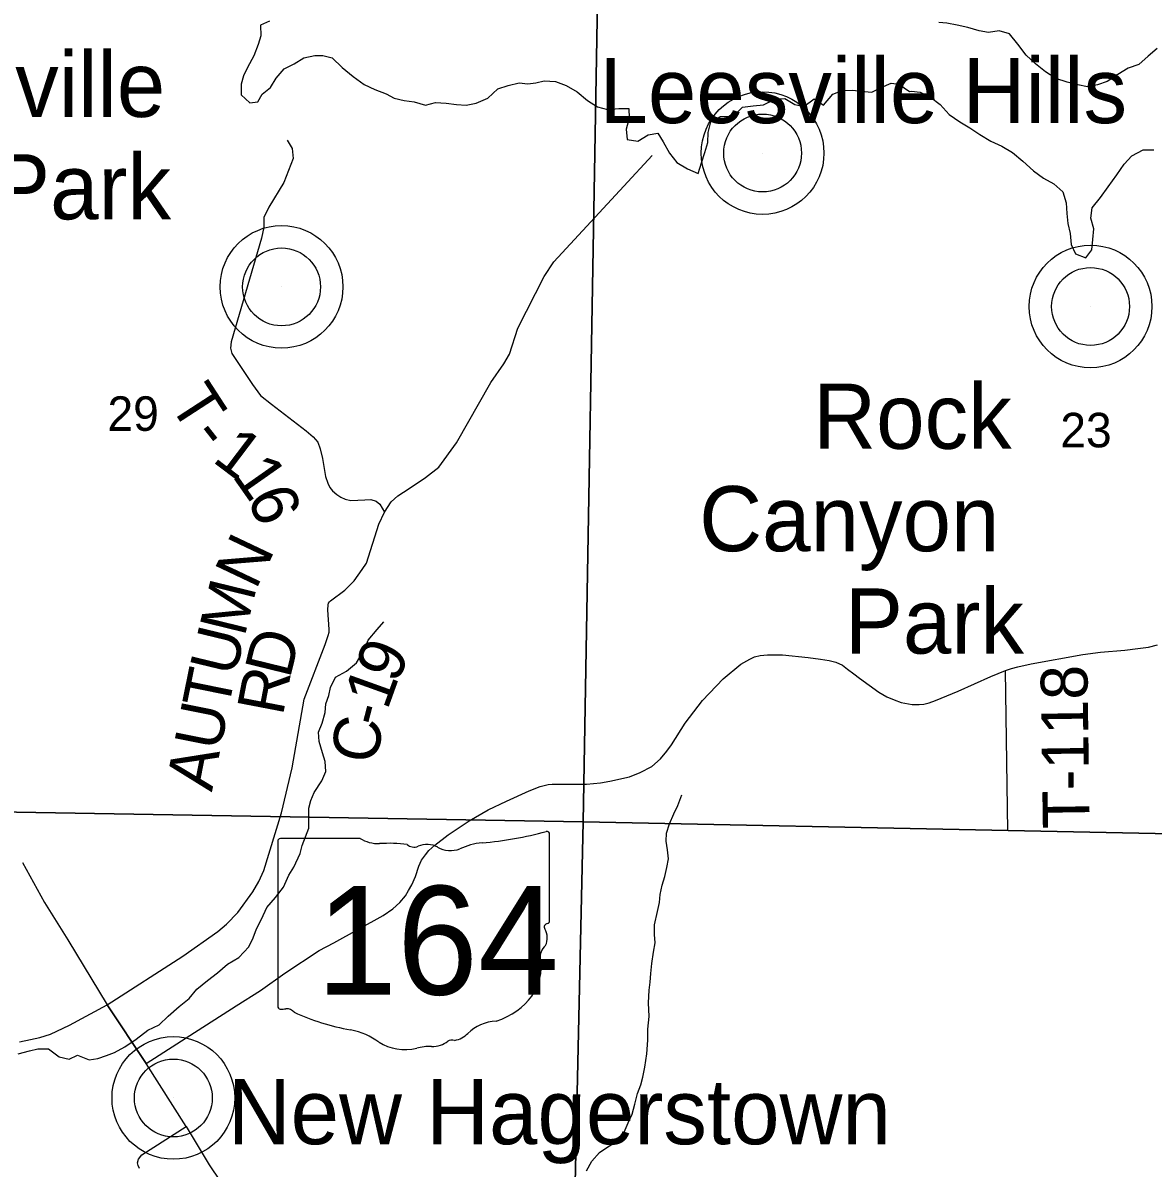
# Model space of a CAD drawing. Extents: x 0 to 34, y 0 to 22.
# Drawn here: x 4.921 to 6.292, y 18.562 to 19.951 of the extents above; entities that cross this region are included whole.
import ezdxf

# ---------------------------------------------------------------- set-up
doc = ezdxf.new("R2010")
doc.units = 0
for name, color, linetype in [('GM_X_Corporation', 7, 'Continuous'), ('GM_X_Corporation_Text', 7, 'Continuous'), ('GM_X_County_Road_Text', 7, 'Continuous'), ('GM_X_Interchange_Ramps', 7, 'Continuous'), ('GM_X_Interstate_Route', 7, 'Continuous'), ('GM_X_Major_Lake', 7, 'Continuous'), ('GM_X_Minor_Lake', 7, 'Continuous'), ('GM_X_Section', 7, 'Continuous'), ('GM_X_State_Location', 7, 'Continuous'), ('GM_X_State_Shield', 7, 'Continuous'), ('GM_X_Township_Road_Text', 7, 'Continuous'), ('GM_X_Township_Text', 7, 'Continuous'), ('GM_X_Unincorporated_Location', 7, 'Continuous'), ('GM_X_Unincorporated_Text', 7, 'Continuous')]:
    doc.layers.add(name, color=color, linetype=linetype)

msp = doc.modelspace()

# ---------------------------------------------------------------- linework, layer by layer
at = {"layer": 'GM_X_Corporation'}
for p, q in [((5.6497, 19.7531), (5.684, 19.7902)), ((5.0706, 18.689), (5.0232, 18.7603))]:
    msp.add_line(p, q, dxfattribs=at)
for points in [[(5.0232, 18.7603), (5.1149, 18.8193), (5.1573, 18.849), (5.168, 18.8579), (5.1818, 18.8722), (5.1997, 18.8972), (5.2071, 18.9099), (5.213, 18.9229), (5.2346, 18.9929), (5.2474, 19.0474), (5.2623, 19.1309), (5.2874, 19.1971), (5.2914, 19.2079), (5.2923, 19.2121), (5.2925, 19.2155), (5.2909, 19.239), (5.2912, 19.2451), (5.2917, 19.2471), (5.2928, 19.2488), (5.2941, 19.2501), (5.3114, 19.2629), (5.3227, 19.2742), (5.3326, 19.288), (5.3375, 19.2957), (5.3527, 19.3431), (5.3596, 19.3576), (5.3676, 19.3703), (5.3755, 19.3776), (5.3894, 19.3861), (5.4094, 19.3998), (5.4256, 19.4123), (5.4467, 19.4415), (5.4884, 19.515), (5.5044, 19.5373), (5.5111, 19.5492), (5.5212, 19.5809), (5.5532, 19.6434), (5.5647, 19.6611), (5.6497, 19.7531)], [(5.0624, 18.5617), (5.061, 18.5652), (5.06, 18.5687), (5.0613, 18.5731), (5.0651, 18.5783), (5.119, 18.6126), (5.0706, 18.689)]]:
    msp.add_lwpolyline(points, dxfattribs=at)
at = {"layer": 'GM_X_Interchange_Ramps'}
msp.add_line((5.0232, 18.7603), (5.0706, 18.689), dxfattribs=at)
for points in [[(5.0706, 18.689), (5.1292, 18.7267), (5.164, 18.7487), (5.1798, 18.759), (5.2091, 18.7777), (5.2388, 18.7987), (5.2802, 18.8259), (5.2979, 18.8354), (5.3577, 18.8684), (5.3697, 18.8766), (5.3783, 18.8844), (5.385, 18.8922), (5.3888, 18.8986), (5.3928, 18.9058), (5.397, 18.9157), (5.401, 18.9282), (5.4045, 18.9354), (5.4092, 18.9422), (5.4134, 18.9473), (5.4204, 18.9538), (5.4366, 18.9664), (5.462, 18.9833), (5.4853, 18.9965), (5.5076, 19.0073), (5.535, 19.0197), (5.5484, 19.0249), (5.558, 19.0274), (5.563, 19.0276), (5.572, 19.0279), (5.5909, 19.0276), (5.6045, 19.0278), (5.6215, 19.0293), (5.6327, 19.0312), (5.6564, 19.0365), (5.6694, 19.0419), (5.6835, 19.049), (5.694, 19.0583), (5.702, 19.0678), (5.7076, 19.0754), (5.7243, 19.1019), (5.745, 19.1291), (5.7703, 19.1554), (5.7916, 19.1732), (5.8025, 19.1794), (5.8082, 19.1823), (5.8152, 19.1836), (5.8238, 19.1845), (5.8423, 19.1844), (5.8733, 19.1813), (5.8882, 19.1795), (5.8986, 19.1778), (5.9069, 19.1756), (5.9148, 19.1719), (5.9211, 19.1674), (5.9285, 19.1617), (5.9357, 19.1562), (5.9589, 19.1395), (5.9686, 19.1338), (5.9774, 19.13), (5.9862, 19.1267), (5.9995, 19.1242), (6.0077, 19.1243), (6.0136, 19.1249), (6.0201, 19.1263), (6.0278, 19.1291), (6.055, 19.1407), (6.0949, 19.1585), (6.1126, 19.1655), (6.1199, 19.168), (6.1274, 19.17), (6.1436, 19.1735), (6.2065, 19.1851), (6.2277, 19.1878), (6.2571, 19.1904), (6.273, 19.1922), (6.2861, 19.194), (6.297, 19.1967)], [(4.9171, 18.7154), (4.9304, 18.718), (4.9415, 18.7205), (4.9546, 18.7247), (4.9777, 18.7354), (5.0232, 18.7603)]]:
    msp.add_lwpolyline(points, dxfattribs=at)
at = {"layer": 'GM_X_Interstate_Route'}
msp.add_line((6.1153, 18.9712), (6.1126, 19.1655), dxfattribs=at)
for points in [[(5.2413, 19.8086), (5.2476, 19.7988), (5.2486, 19.7863), (5.2376, 19.7572), (5.2191, 19.7276), (5.2132, 19.715), (5.213, 19.7032), (5.2102, 19.6899), (5.1736, 19.5642), (5.1726, 19.5566), (5.1742, 19.5501), (5.1995, 19.5124), (5.2093, 19.4989), (5.2224, 19.4887), (5.2644, 19.4564), (5.273, 19.4491), (5.2787, 19.4425), (5.2816, 19.4343), (5.2844, 19.4225), (5.2879, 19.4008), (5.2907, 19.3927), (5.2933, 19.3877), (5.2966, 19.3833), (5.3016, 19.379), (5.3067, 19.3759), (5.312, 19.3734), (5.3186, 19.3718), (5.3356, 19.3726), (5.343, 19.3728), (5.3493, 19.3711), (5.3539, 19.3672), (5.3596, 19.3576)], [(4.9206, 18.9329), (4.9472, 18.8843), (4.9755, 18.8388), (5.0232, 18.7603)], [(5.119, 18.6126), (5.1469, 18.5663), (5.1854, 18.5091), (5.2146, 18.4601), (5.2322, 18.4179), (5.2451, 18.394), (5.2571, 18.3728), (5.375, 18.2318), (5.4932, 18.0957), (5.5117, 18.0772), (5.5291, 18.0622), (5.5398, 18.0515), (5.5566, 18.0389), (5.5686, 18.0335), (5.5781, 18.0252), (5.5919, 18.0144), (5.6341, 17.955)]]:
    msp.add_lwpolyline(points, dxfattribs=at)
at = {"layer": 'GM_X_Minor_Lake'}
for points in [[(4.6053, 19.9945), (5.6176, 19.9781), (5.6006, 18.9822), (4.5812, 18.9996)], [(6.6462, 19.9578), (6.6311, 18.9612), (5.6006, 18.9822), (5.6176, 19.9781)], [(4.5812, 18.9996), (5.6006, 18.9822), (5.5776, 17.9596), (4.5642, 17.9795)], [(5.6006, 18.9822), (6.6311, 18.9612), (6.6, 17.9446), (5.5776, 17.9596)]]:
    msp.add_lwpolyline(points, close=True, dxfattribs=at)
at = {"layer": 'GM_X_State_Location'}
for p, q in [((5.818, 19.7931), (5.818, 19.7931)), ((5.2347, 19.6308), (5.2347, 19.6308)), ((6.2157, 19.607), (6.2157, 19.607)), ((5.1035, 18.6472), (5.1035, 18.6472))]:
    msp.add_line(p, q, dxfattribs=at)
at = {"layer": 'GM_X_State_Shield'}
for centre, radius in [((5.818, 19.7931), 0.0744), ((5.818, 19.7931), 0.0472), ((5.2347, 19.6308), 0.0744), ((6.2157, 19.607), 0.0744), ((5.2347, 19.6308), 0.0472), ((6.2157, 19.607), 0.0472), ((5.1035, 18.6472), 0.0744), ((5.1035, 18.6472), 0.0472)]:
    msp.add_circle(centre, radius, dxfattribs=at)
at = {"layer": 'GM_X_Township_Road_Text'}
for points in [[(4.9154, 18.7007), (4.929, 18.7042), (4.9392, 18.7069), (4.9522, 18.7067), (4.9652, 18.6969), (4.9773, 18.6944), (4.9872, 18.699), (5.0013, 18.6934), (5.0119, 18.695), (5.0225, 18.6985), (5.0323, 18.7024), (5.0448, 18.7094), (5.0584, 18.7186), (5.0724, 18.7293), (5.0864, 18.7359), (5.0973, 18.7462), (5.1105, 18.7581), (5.1226, 18.7677), (5.132, 18.7792), (5.1448, 18.7895), (5.1569, 18.7991), (5.1693, 18.8095), (5.1829, 18.8176), (5.195, 18.8306), (5.2002, 18.8412), (5.2043, 18.8523), (5.2102, 18.8641), (5.217, 18.8782), (5.2275, 18.8901), (5.2369, 18.903), (5.2436, 18.9175), (5.2496, 18.9271), (5.2574, 18.9438), (5.2596, 18.9533), (5.2678, 18.9743), (5.2676, 18.9986), (5.2702, 19.0081), (5.2743, 19.0176), (5.2836, 19.0317), (5.2885, 19.0432), (5.2876, 19.0553), (5.2845, 19.0659), (5.2802, 19.0795), (5.2793, 19.0909), (5.2838, 19.1019), (5.2875, 19.1145), (5.2885, 19.1251), (5.2919, 19.1354), (5.2941, 19.1449), (5.3, 19.1575), (5.3136, 19.1648), (5.3257, 19.1748), (5.3347, 19.1908), (5.3399, 19.2022), (5.3508, 19.2152), (5.3587, 19.2248)], [(5.6777, 18.7007), (5.6787, 18.7174), (5.679, 18.7307), (5.6803, 18.7459), (5.6798, 18.7626), (5.6805, 18.7778), (5.6815, 18.7877), (5.6826, 18.7983), (5.6836, 18.8101), (5.6858, 18.8241), (5.6876, 18.8352), (5.6871, 18.8454), (5.687, 18.8572), (5.6907, 18.8735), (5.6929, 18.8842), (5.6939, 18.894), (5.6961, 18.9054), (5.6994, 18.9157), (5.702, 18.9268), (5.7038, 18.937), (5.7026, 18.948), (5.701, 18.9586), (5.7016, 18.9685), (5.7053, 18.9795), (5.7105, 18.9917), (5.7154, 19.002), (5.7202, 19.015)], [(5.6044, 18.5589), (5.6108, 18.5707), (5.6202, 18.581), (5.6304, 18.5879), (5.6417, 18.5949), (5.65, 18.6056), (5.6548, 18.617), (5.6597, 18.6277), (5.663, 18.6398), (5.6663, 18.6528), (5.6704, 18.6631), (5.6726, 18.6726), (5.6752, 18.6844), (5.6777, 18.7007)]]:
    msp.add_lwpolyline(points, dxfattribs=at)
at = {"layer": 'GM_X_Unincorporated_Location'}
for points in [[(5.2201, 19.9532), (5.2092, 19.9481), (5.2094, 19.9352), (5.2065, 19.9249), (5.2011, 19.9111), (5.1933, 19.897), (5.1885, 19.8866), (5.1857, 19.8767), (5.1859, 19.8635), (5.1963, 19.8538), (5.2058, 19.8551), (5.211, 19.8646), (5.2211, 19.8724), (5.2281, 19.8839), (5.2378, 19.8954), (5.2499, 19.9013), (5.2615, 19.9087), (5.2752, 19.9112), (5.2847, 19.9114), (5.2961, 19.9085), (5.3081, 19.897), (5.3216, 19.8858), (5.3347, 19.8762), (5.3477, 19.8703), (5.3615, 19.8648), (5.3711, 19.8597), (5.3833, 19.8569), (5.3955, 19.8552), (5.4092, 19.8512), (5.4214, 19.8544), (5.4343, 19.8535), (5.4469, 19.8518), (5.4587, 19.8513), (5.4708, 19.8537), (5.4847, 19.8597), (5.4971, 19.8709), (5.5096, 19.8749), (5.5228, 19.8781), (5.5335, 19.8772), (5.543, 19.8781), (5.5532, 19.8805), (5.5669, 19.88), (5.5799, 19.8749), (5.5933, 19.8672), (5.6057, 19.8567), (5.6176, 19.849), (5.6298, 19.8461), (5.6435, 19.8471), (5.6556, 19.8473), (5.6562, 19.8352), (5.6526, 19.8222), (5.6536, 19.8094), (5.6666, 19.8073), (5.6794, 19.8151), (5.6911, 19.8172), (5.6974, 19.8067), (5.7052, 19.7931), (5.7138, 19.7815), (5.7268, 19.7738), (5.7398, 19.7683), (5.7438, 19.7813), (5.7478, 19.7938), (5.7514, 19.806), (5.7519, 19.8182), (5.7551, 19.8311), (5.7668, 19.8374), (5.7824, 19.8377), (5.7936, 19.8489), (5.8065, 19.8502), (5.819, 19.8516), (5.8334, 19.8586), (5.8448, 19.8592), (5.857, 19.8518), (5.8681, 19.8497), (5.8805, 19.859), (5.892, 19.8513), (5.9032, 19.8643), (5.9145, 19.8691), (5.9271, 19.8693), (5.9374, 19.8683), (5.9503, 19.867), (5.9616, 19.8725), (5.9737, 19.8777), (5.9832, 19.8767), (5.9963, 19.8678)], [(6.2965, 19.9198), (6.2856, 19.9106), (6.2744, 19.9005), (6.2612, 19.8961), (6.2488, 19.8883), (6.236, 19.8798), (6.2239, 19.8758), (6.2121, 19.8733), (6.2003, 19.8757), (6.1873, 19.8789), (6.1736, 19.8833), (6.1609, 19.8914), (6.1489, 19.9014), (6.1374, 19.9119), (6.1273, 19.925), (6.1172, 19.9377), (6.1049, 19.9413), (6.0921, 19.9392), (6.0806, 19.9413), (6.0669, 19.9452), (6.0539, 19.948), (6.0413, 19.9505), (6.0318, 19.9515)], [(5.9963, 19.8678), (5.9986, 19.8682), (6.0089, 19.8669), (6.0215, 19.861), (6.0334, 19.8521), (6.0443, 19.8398), (6.057, 19.8309), (6.0693, 19.8235), (6.0816, 19.8157), (6.0946, 19.8076), (6.108, 19.8014), (6.1211, 19.7936), (6.1334, 19.7832), (6.1465, 19.7717), (6.1588, 19.7628), (6.1711, 19.7558), (6.1819, 19.7461), (6.186, 19.7329), (6.1869, 19.7196), (6.1883, 19.7075), (6.1908, 19.6954), (6.1921, 19.6821), (6.1976, 19.6708), (6.2099, 19.6661), (6.2173, 19.6757), (6.2186, 19.6883), (6.2196, 19.7012), (6.2159, 19.714), (6.2176, 19.7266), (6.2277, 19.7392), (6.237, 19.7523), (6.2474, 19.7665), (6.2566, 19.7796), (6.2656, 19.7896), (6.2795, 19.797), (6.2925, 19.7969)]]:
    msp.add_lwpolyline(points, dxfattribs=at)
at = {"layer": 'GM_X_Unincorporated_Text'}
for p, q in [((5.2302, 18.9585), (5.2302, 18.7584)), ((5.3299, 18.962), (5.2334, 18.962)), ((5.5597, 18.8623), (5.5597, 18.9669)), ((5.5597, 18.8623), (5.5597, 18.8623))]:
    msp.add_line(p, q, dxfattribs=at)
for centre, major_axis, start_param, end_param in [((5.2339, 18.959), (0.00382, 0), 1.712693, 3.28349), ((5.3529, 18.9852), (0.037, 0), 4.042523, 4.731795), ((5.4423, 19.2348), (0.3495, 0), 4.814394, 5.042369), ((5.5561, 18.9674), (0.00367, 0), 6.141152, 7.989035), ((5.3652, 18.8496), (0.133, 0), 1.404758, 1.657858), ((5.3954, 18.96), (0.0107, 0), 3.836095, 5.185415), ((5.4111, 18.9369), (0.0222, 0), 0.950623, 2.079405), ((5.4397, 18.9686), (0.0267, 0), 4.081561, 5.145723), ((5.4869, 18.9009), (0.0703, 0), 1.699011, 2.107814), ((5.5558, 18.8618), (0.00393, 0), 5.05454, 6.418171), ((5.5589, 18.8546), (0.00568, 0), 1.883978, 3.671073), ((5.5228, 18.8413), (0.0341, 0), 5.934695, 6.695948), ((5.5729, 18.8184), (0.0248, 0), 2.387724, 3.262537), ((5.4619, 18.8051), (0.0874, 0), 5.101752, 6.440018), ((5.234, 18.758), (0.00385, 0), 3.00124, 4.508301), ((5.2345, 18.7785), (0.0294, 0), 4.665946, 4.897461), ((5.2406, 18.7469), (0.0106, 0), 0.519207, 1.627899), ((5.3744, 18.9267), (0.2524, 0), 4.195997, 4.488961), ((5.4988, 18.7022), (0.0479, 0), 1.647645, 2.488434), ((5.2991, 18.6685), (0.079, 0), 0.823519, 1.323587), ((5.4381, 18.739), (0.0282, 0), 4.937069, 5.64225), ((5.3846, 18.7459), (0.0501, 0), 4.026481, 4.996735), ((5.4135, 18.6767), (0.0412, 0), 1.495662, 1.94098), ((5.4172, 18.7309), (0.0267, 0), 4.691044, 5.507374), ((5.4413, 18.7115), (0.00752, 0), 1.147584, 2.315152)]:
    msp.add_ellipse(centre, major_axis=major_axis, ratio=0.8, start_param=start_param, end_param=end_param, dxfattribs=at)

# ---------------------------------------------------------------- texts
at = {"layer": 'GM_X_Corporation_Text'}
for s, height, p in [('Leesville', 0.07898, (4.6827, 19.8369)), ('Leesville Hills', 0.078977, (5.6202, 19.8294)), ('Lake Park', 0.07898, (4.6252, 19.7127)), ('Rock', 0.07898, (5.8794, 19.4344)), ('Canyon', 0.07898, (5.7411, 19.3102)), ('Park', 0.07898, (5.9177, 19.1861)), ('New Hagerstown', 0.078977, (5.1694, 18.5911))]:
    msp.add_text(s, height=height, rotation=0, dxfattribs=at).set_placement(p)
at = {"layer": 'GM_X_County_Road_Text'}
for s, p in [('29', (5.0236, 19.4562)), ('23', (6.179, 19.4362))]:
    msp.add_text(s, height=0.04186, rotation=0, dxfattribs=at).set_placement(p)
at = {"layer": 'GM_X_Major_Lake'}
for s, rotation, p in [('N', 64.6063, (5.2035, 19.2623)), ('M', 76.2281, (5.1898, 19.2053)), ('U', 76.383, (5.1781, 19.1567)), ('D', 76.2553, (5.2447, 19.1545)), ('9', 66.4608, (5.3743, 19.1484)), ('T', 78.5148, (5.1697, 19.1156)), ('R', 79.1355, (5.2361, 19.1094)), ('1', 70.2583, (5.3628, 19.1164)), ('U', 78.7554, (5.16, 19.0666)), ('-', 75.3371, (5.3573, 19.0951)), ('C', 79.6477, (5.3492, 19.0503)), ('A', 78.7554, (5.1502, 19.0176))]:
    msp.add_text(s, height=0.0568, rotation=rotation, dxfattribs=at).set_placement(p)
at = {"layer": 'GM_X_Section'}
for s, height, rotation, p in [('T', 0.0568, 302.9674, (5.0972, 19.4896)), ('-', 0.0568, 308.0466, (5.1235, 19.4495)), ('1', 0.0568, 322.8642, (5.1493, 19.4199)), ('1', 0.0568, 305.0383, (5.1739, 19.4021)), ('6', 0.0568, 291.6333, (5.1924, 19.3765)), ('T-118', 0.05682, 90.8431, (6.2147, 18.9742))]:
    msp.add_text(s, height=height, rotation=rotation, dxfattribs=at).set_placement(p)
at = {"layer": 'GM_X_Township_Text'}
for s in ['s', 'r']:
    msp.add_text(s, height=0.000189, dxfattribs=at).set_placement((5.3912, 18.8452))
msp.add_text('164', height=0.000189, rotation=0, dxfattribs=at).set_placement((5.3244, 18.8314))
at = {"layer": 'GM_X_Unincorporated_Text'}
msp.add_text('164', height=0.13184, dxfattribs=at).set_placement((5.2767, 18.7725))

doc.saveas('drawing.dxf')
